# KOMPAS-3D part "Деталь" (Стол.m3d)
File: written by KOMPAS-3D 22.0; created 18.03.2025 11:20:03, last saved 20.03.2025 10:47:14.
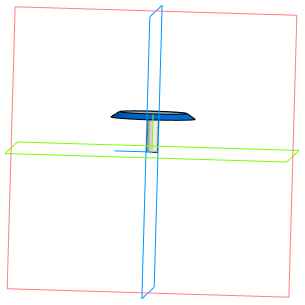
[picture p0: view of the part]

Document properties: Автор: Пользователь Windows; Полное имя файла: C:\Users\Student\Documents\Картошечка\База Сабнатика\Мебель\Стол.m3d

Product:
- Part/product: Деталь
    Масса: 0.001277

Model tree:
1. Эскиз:1
2. Элемент вращения:1
     Угол 1 = 360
